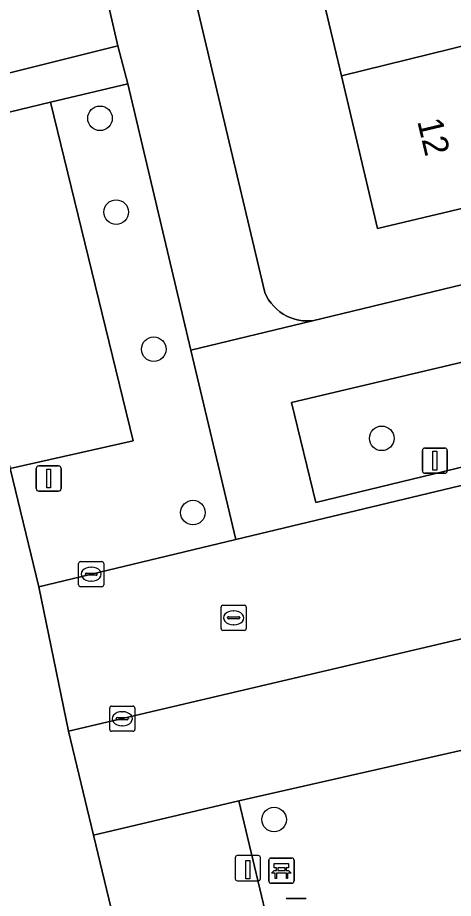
# Model space of a CAD drawing. Extents: x 158031 to 159244, y 380104 to 381214.
# Drawn here: x 158542.1 to 158559.44, y 380761.24 to 380796.3 of the extents above; entities that cross this region are included whole.
import ezdxf

# ---------------------------------------------------------------- set-up
doc = ezdxf.new("R2010")
doc.units = 0
for name, color, linetype in [('IMGEO_Afvalbak', 7, 'Continuous'), ('IMGEO_Bank', 7, 'Continuous'), ('IMGEO_Boom', 7, 'Continuous'), ('IMGEO_Erf', 7, 'Continuous'), ('IMGEO_Groenvoorziening', 7, 'Continuous'), ('IMGEO_Kolk', 7, 'Continuous'), ('IMGEO_Laadpaal', 7, 'Continuous'), ('IMGEO_Lichtmast', 7, 'Continuous'), ('IMGEO_Pand', 7, 'Continuous'), ('IMGEO_Pand_nummerreeks', 7, 'Continuous'), ('IMGEO_Parkeervlak_open', 7, 'Continuous'), ('IMGEO_Rijbaan_lokaal_open', 7, 'Continuous'), ('IMGEO_Rioolput', 7, 'Continuous'), ('IMGEO_Voetpad_open', 7, 'Continuous')]:
    doc.layers.add(name, color=color, linetype=linetype)

msp = doc.modelspace()

# ---------------------------------------------------------------- linework, layer by layer
at = {"layer": 'IMGEO_Afvalbak'}
for p, q in [((158552.789, 380761.24), (158553.579, 380761.24)), ((158553.579, 380761.24), (158552.789, 380761.24))]:
    msp.add_line(p, q, dxfattribs=at)
at = {"layer": 'IMGEO_Bank'}
for p, q in [((158552.1, 380761.919), (158552.1, 380762.76)), ((158552.1, 380762.76), (158552.1, 380761.919)), ((158552.175, 380762.844), (158553.016, 380762.844)), ((158553.016, 380762.844), (158552.175, 380762.844)), ((158553.1, 380762.769), (158553.1, 380761.928)), ((158553.1, 380761.928), (158553.1, 380762.769)), ((158552.409, 380762.35), (158552.409, 380762.456)), ((158552.453, 380762.456), (158552.453, 380762.35)), ((158552.741, 380762.462), (158552.459, 380762.462)), ((158552.459, 380762.344), (158552.741, 380762.344)), ((158552.747, 380762.35), (158552.747, 380762.456)), ((158552.791, 380762.456), (158552.791, 380762.35)), ((158552.797, 380762.242), (158552.404, 380762.242)), ((158553.025, 380761.844), (158552.184, 380761.844)), ((158552.184, 380761.844), (158553.025, 380761.844))]:
    msp.add_line(p, q, dxfattribs=at)
for points in [[(158552.403, 380762.462), (158552.317, 380762.462), (158552.317, 380762.623), (158552.88, 380762.623), (158552.88, 380762.462), (158552.797, 380762.462)], [(158552.347, 380762.242), (158552.205, 380762.242), (158552.317, 380762.344), (158552.403, 380762.344)], [(158552.797, 380762.344), (158552.88, 380762.344), (158552.992, 380762.242), (158552.853, 380762.242)], [(158552.397, 380762.235), (158552.397, 380762.028), (158552.354, 380762.028), (158552.354, 380762.235)], [(158552.847, 380762.235), (158552.847, 380762.028), (158552.803, 380762.028), (158552.803, 380762.235)]]:
    msp.add_lwpolyline(points, dxfattribs=at)
for centre, radius, start, end in [((158552.178, 380762.766), 0.0779, 92.4484, 184.2845), ((158552.178, 380762.766), 0.0779, 92.4484, 184.2845), ((158553.022, 380762.766), 0.0779, 2.4484, 94.2845), ((158553.022, 380762.766), 0.0779, 2.4484, 94.2845), ((158552.402, 380762.455), 0.00671, 2.8957, 87.1043), ((158552.402, 380762.351), 0.00671, 272.8957, 357.1043), ((158552.459, 380762.455), 0.00671, 92.8957, 177.1043), ((158552.459, 380762.351), 0.00671, 182.8957, 267.1043), ((158552.741, 380762.455), 0.00671, 2.8957, 87.1043), ((158552.741, 380762.351), 0.00671, 272.8957, 357.1043), ((158552.798, 380762.455), 0.00671, 92.8957, 177.1043), ((158552.798, 380762.351), 0.00671, 182.8957, 267.1043), ((158552.178, 380761.922), 0.0779, 182.4484, 274.2845), ((158552.178, 380761.922), 0.0779, 182.4484, 274.2845), ((158552.347, 380762.235), 0.00671, 2.8957, 87.1043), ((158552.404, 380762.235), 0.00671, 92.8957, 177.1043), ((158552.796, 380762.235), 0.00671, 2.8957, 87.1043), ((158552.853, 380762.235), 0.00671, 92.8957, 177.1043), ((158553.022, 380761.922), 0.0779, 272.4484, 4.2845), ((158553.022, 380761.922), 0.0779, 272.4484, 4.2845)]:
    msp.add_arc(centre, radius, start, end, dxfattribs=at)
at = {"layer": 'IMGEO_Boom'}
for centre in [(158545.379, 380792.292), (158546.022, 380788.557), (158547.52, 380783.101), (158556.593, 380779.552), (158549.077, 380776.596), (158552.309, 380764.378)]:
    msp.add_circle(centre, 0.489, dxfattribs=at)
at = {"layer": 'IMGEO_Erf'}
for points in [[(158544.566, 380816.468), (158551.938, 380785.363), (158552.008, 380785.214), (158552.091, 380785.071), (158552.186, 380784.936), (158552.293, 380784.811), (158552.411, 380784.695), (158552.539, 380784.591), (158552.675, 380784.498), (158552.82, 380784.418), (158552.971, 380784.351), (158553.127, 380784.298), (158553.287, 380784.259), (158553.45, 380784.234), (158553.615, 380784.224), (158553.78, 380784.229), (158553.836, 380784.234), (158575.794, 380789.538), (158568.094, 380822.042)], [(158562.747, 380800.007), (158563.667, 380796.124), (158564.626, 380792.079), (158569.966, 380793.345), (158570.391, 380791.548), (158565.064, 380790.285), (158565.138, 380789.974), (158556.423, 380787.909), (158554.986, 380793.976), (158553.597, 380799.838)]]:
    msp.add_lwpolyline(points, dxfattribs=at)
at = {"layer": 'IMGEO_Groenvoorziening'}
for points in [[(158538.226, 380793.212), (158546.085, 380795.171), (158543.309, 380807.269), (158533.158, 380804.845), (158533.865, 380801.959), (158534.897, 380797.743), (158537.111, 380798.246), (158538.129, 380793.613)], [(158546.49, 380793.669), (158543.412, 380792.934), (158546.695, 380779.447), (158541.806, 380778.346), (158542.939, 380773.643), (158550.781, 380775.523), (158548.998, 380783.065)], [(158577.413, 380782.673), (158576.522, 380786.533), (158552.994, 380780.981), (158553.963, 380777.002)]]:
    msp.add_lwpolyline(points, close=True, dxfattribs=at)
at = {"layer": 'IMGEO_Kolk'}
for p, q in [((158544.529, 380773.719), (158544.529, 380774.571)), ((158544.604, 380774.645), (158545.456, 380774.645)), ((158545.53, 380774.571), (158545.53, 380773.719)), ((158544.831, 380774.188), (158545.229, 380774.188)), ((158545.017, 380774.425), (158545.042, 380774.425)), ((158544.788, 380774.139), (158544.788, 380774.151)), ((158545.226, 380774.102), (158544.828, 380774.102)), ((158545.04, 380773.865), (158545.015, 380773.865)), ((158545.272, 380774.151), (158545.272, 380774.139)), ((158545.456, 380773.645), (158544.604, 380773.645)), ((158545.764, 380767.965), (158545.764, 380768.817)), ((158545.839, 380768.891), (158546.691, 380768.891)), ((158546.252, 380768.671), (158546.277, 380768.671)), ((158546.765, 380768.817), (158546.765, 380767.965)), ((158546.023, 380768.385), (158546.023, 380768.397)), ((158546.461, 380768.348), (158546.063, 380768.348)), ((158546.066, 380768.434), (158546.464, 380768.434)), ((158546.507, 380768.397), (158546.507, 380768.385)), ((158546.691, 380767.891), (158545.839, 380767.891)), ((158546.275, 380768.111), (158546.25, 380768.111))]:
    msp.add_line(p, q, dxfattribs=at)
for points in [[(158544.529, 380773.719), (158544.529, 380774.571)], [(158544.604, 380774.645), (158545.456, 380774.645)], [(158545.53, 380774.571), (158545.53, 380773.719)], [(158545.456, 380773.645), (158544.604, 380773.645)], [(158545.764, 380767.965), (158545.764, 380768.817)], [(158545.839, 380768.891), (158546.691, 380768.891)], [(158546.765, 380768.817), (158546.765, 380767.965)], [(158546.691, 380767.891), (158545.839, 380767.891)]]:
    msp.add_lwpolyline(points, dxfattribs=at)
for centre, radius, start, end in [((158544.606, 380774.569), 0.0765, 91.552, 178.448), ((158544.606, 380774.569), 0.0765, 91.552, 178.448), ((158545.454, 380774.569), 0.0765, 1.552, 88.448), ((158545.454, 380774.569), 0.0765, 1.552, 88.448), ((158544.828, 380774.148), 0.0403, 85.8775, 175.7526), ((158545.233, 380774.15), 0.0386, 1.7309, 96.639), ((158544.825, 380774.138), 0.0366, 178.938, 274.7102), ((158545.229, 380774.145), 0.043, 264.8664, 352.4533), ((158544.606, 380773.721), 0.0765, 181.552, 268.448), ((158544.606, 380773.721), 0.0765, 181.552, 268.448), ((158545.454, 380773.721), 0.0765, 271.552, 358.448), ((158545.454, 380773.721), 0.0765, 271.552, 358.448), ((158545.841, 380768.815), 0.0765, 91.552, 178.448), ((158545.841, 380768.815), 0.0765, 91.552, 178.448), ((158546.689, 380768.815), 0.0765, 1.552, 88.448), ((158546.689, 380768.815), 0.0765, 1.552, 88.448), ((158546.063, 380768.394), 0.0403, 85.8775, 175.7526), ((158546.06, 380768.384), 0.0366, 178.938, 274.7102), ((158546.464, 380768.391), 0.043, 264.8664, 352.4533), ((158546.468, 380768.396), 0.0386, 1.7309, 96.639), ((158545.841, 380767.967), 0.0765, 181.552, 268.448), ((158545.841, 380767.967), 0.0765, 181.552, 268.448), ((158546.689, 380767.967), 0.0765, 271.552, 358.448), ((158546.689, 380767.967), 0.0765, 271.552, 358.448)]:
    msp.add_arc(centre, radius, start, end, dxfattribs=at)
for centre, major_axis, ratio, start_param, end_param in [((158545.016, 380774.145), (-0.387, 0.002), 0.722429, 4.712389, 7.853982), ((158545.041, 380774.145), (-0.39, 0.002), 0.717154, 1.570796, 4.712389), ((158546.251, 380768.391), (-0.387, 0.002), 0.722429, 4.712389, 7.853982), ((158546.276, 380768.391), (-0.39, 0.002), 0.717154, 1.570796, 4.712389)]:
    msp.add_ellipse(centre, major_axis=major_axis, ratio=ratio, start_param=start_param, end_param=end_param, dxfattribs=at)
at = {"layer": 'IMGEO_Laadpaal'}
for p, q in [((158550.763, 380762.857), (158550.763, 380762.016)), ((158550.763, 380762.857), (158550.763, 380762.016)), ((158551.679, 380762.941), (158550.838, 380762.941)), ((158551.679, 380762.941), (158550.838, 380762.941)), ((158551.763, 380762.025), (158551.763, 380762.866)), ((158551.763, 380762.025), (158551.763, 380762.866)), ((158550.847, 380761.941), (158551.688, 380761.941)), ((158550.847, 380761.941), (158551.688, 380761.941))]:
    msp.add_line(p, q, dxfattribs=at)
msp.add_lwpolyline([(158551.178, 380762.754), (158551.338, 380762.754), (158551.338, 380762.021), (158551.178, 380762.021), (158551.178, 380762.754)], dxfattribs=at)
for centre, start, end in [((158550.841, 380762.863), 92.4484, 184.2845), ((158550.841, 380762.863), 92.4484, 184.2845), ((158551.685, 380762.863), 2.4484, 94.2845), ((158551.685, 380762.863), 2.4484, 94.2845), ((158550.841, 380762.019), 182.4484, 274.2845), ((158550.841, 380762.019), 182.4484, 274.2845), ((158551.685, 380762.019), 272.4484, 4.2845), ((158551.685, 380762.019), 272.4484, 4.2845)]:
    msp.add_arc(centre, 0.0779, start, end, dxfattribs=at)
at = {"layer": 'IMGEO_Lichtmast'}
for p, q in [((158558.31, 380779.163), (158559.1, 380779.163)), ((158559.1, 380779.163), (158558.31, 380779.163)), ((158558.21, 380778.263), (158558.21, 380779.063)), ((158558.21, 380779.063), (158558.21, 380778.263)), ((158559.2, 380779.063), (158559.2, 380778.263)), ((158559.2, 380778.263), (158559.2, 380779.063)), ((158542.94, 380778.453), (158543.73, 380778.453)), ((158543.73, 380778.453), (158542.94, 380778.453)), ((158542.84, 380777.553), (158542.84, 380778.353)), ((158542.84, 380778.353), (158542.84, 380777.553)), ((158543.83, 380778.353), (158543.83, 380777.553)), ((158543.83, 380777.553), (158543.83, 380778.353)), ((158559.1, 380778.163), (158558.31, 380778.163)), ((158558.31, 380778.163), (158559.1, 380778.163)), ((158543.73, 380777.453), (158542.94, 380777.453)), ((158542.94, 380777.453), (158543.73, 380777.453))]:
    msp.add_line(p, q, dxfattribs=at)
for points in [[(158558.63, 380779.038), (158558.78, 380779.038), (158558.78, 380778.288), (158558.63, 380778.288), (158558.63, 380779.038)], [(158543.26, 380778.328), (158543.41, 380778.328), (158543.41, 380777.578), (158543.26, 380777.578), (158543.26, 380778.328)]]:
    msp.add_lwpolyline(points, dxfattribs=at)
for centre, start, end in [((158558.31, 380779.063), 90, 180), ((158558.31, 380779.063), 90, 180), ((158559.1, 380779.063), 0, 90), ((158559.1, 380779.063), 360, 90), ((158542.94, 380778.353), 90, 180), ((158542.94, 380778.353), 90, 180), ((158543.73, 380778.353), 0, 90), ((158543.73, 380778.353), 360, 90), ((158558.31, 380778.263), 180, 270), ((158558.31, 380778.263), 180, 270), ((158559.1, 380778.263), 270, 0), ((158559.1, 380778.263), 270, 0), ((158542.94, 380777.553), 180, 270), ((158542.94, 380777.553), 180, 270), ((158543.73, 380777.553), 270, 0), ((158543.73, 380777.553), 270, 0)]:
    msp.add_arc(centre, 0.1, start, end, dxfattribs=at)
at = {"layer": 'IMGEO_Pand'}
for points in [[(158563.667, 380796.124), (158562.747, 380800.007), (158568.193, 380801.298), (158567.735, 380803.227), (158553.597, 380799.838), (158554.986, 380793.976)], [(158563.667, 380796.124), (158554.986, 380793.976), (158556.423, 380787.909), (158565.138, 380789.974), (158565.064, 380790.285), (158570.391, 380791.548), (158569.966, 380793.345), (158564.626, 380792.079)]]:
    msp.add_lwpolyline(points, close=True, dxfattribs=at)
at = {"layer": 'IMGEO_Parkeervlak_open'}
for points in [[(158543.412, 380792.934), (158538.573, 380791.773), (158541.806, 380778.346), (158546.695, 380779.447)], [(158547.375, 380754.387), (158553.139, 380755.776), (158550.898, 380765.127), (158545.124, 380763.759)]]:
    msp.add_lwpolyline(points, close=True, dxfattribs=at)
at = {"layer": 'IMGEO_Rijbaan_lokaal_open'}
for points in [[(158541.806, 380778.346), (158538.573, 380791.773), (158538.226, 380793.212), (158538.129, 380793.613), (158535.941, 380793.094), (158520.821, 380789.512), (158516.767, 380788.551), (158525.714, 380750), (158525.882, 380749.276), (158528.927, 380750), (158547.375, 380754.387), (158545.124, 380763.759), (158544.131, 380767.891), (158542.939, 380773.643)], [(158602.537, 380781.61), (158601.167, 380787.602), (158550.781, 380775.523), (158542.939, 380773.643), (158544.131, 380767.891)]]:
    msp.add_lwpolyline(points, close=True, dxfattribs=at)
at = {"layer": 'IMGEO_Rioolput'}
for p, q in [((158550.198, 380771.982), (158550.198, 380772.834)), ((158550.273, 380772.908), (158551.125, 380772.908)), ((158551.199, 380772.834), (158551.199, 380771.982)), ((158550.5, 380772.451), (158550.898, 380772.451)), ((158550.686, 380772.688), (158550.711, 380772.688)), ((158550.457, 380772.402), (158550.457, 380772.414)), ((158550.895, 380772.365), (158550.497, 380772.365)), ((158550.709, 380772.128), (158550.684, 380772.128)), ((158550.941, 380772.414), (158550.941, 380772.402)), ((158551.125, 380771.908), (158550.273, 380771.908))]:
    msp.add_line(p, q, dxfattribs=at)
for points in [[(158550.198, 380771.982), (158550.198, 380772.834)], [(158550.273, 380772.908), (158551.125, 380772.908)], [(158551.199, 380772.834), (158551.199, 380771.982)], [(158551.125, 380771.908), (158550.273, 380771.908)]]:
    msp.add_lwpolyline(points, dxfattribs=at)
for centre, radius, start, end in [((158550.275, 380772.832), 0.0765, 91.552, 178.448), ((158550.275, 380772.832), 0.0765, 91.552, 178.448), ((158551.123, 380772.832), 0.0765, 1.552, 88.448), ((158551.123, 380772.832), 0.0765, 1.552, 88.448), ((158550.497, 380772.411), 0.0403, 85.8775, 175.7526), ((158550.902, 380772.413), 0.0386, 1.7309, 96.639), ((158550.494, 380772.401), 0.0366, 178.938, 274.7102), ((158550.898, 380772.408), 0.043, 264.8664, 352.4533), ((158550.275, 380771.984), 0.0765, 181.552, 268.448), ((158550.275, 380771.984), 0.0765, 181.552, 268.448), ((158551.123, 380771.984), 0.0765, 271.552, 358.448), ((158551.123, 380771.984), 0.0765, 271.552, 358.448)]:
    msp.add_arc(centre, radius, start, end, dxfattribs=at)
for centre, major_axis, ratio, start_param, end_param in [((158550.685, 380772.408), (-0.387, 0.002), 0.722429, 4.712389, 7.853982), ((158550.71, 380772.408), (-0.39, 0.002), 0.717154, 1.570796, 4.712389)]:
    msp.add_ellipse(centre, major_axis=major_axis, ratio=ratio, start_param=start_param, end_param=end_param, dxfattribs=at)
at = {"layer": 'IMGEO_Voetpad_open'}
msp.add_lwpolyline([(158543.309, 380807.269), (158546.085, 380795.171), (158546.49, 380793.669), (158548.998, 380783.065), (158553.836, 380784.234), (158553.78, 380784.229), (158553.615, 380784.224), (158553.45, 380784.234), (158553.287, 380784.259), (158553.127, 380784.298), (158552.971, 380784.351), (158552.82, 380784.418), (158552.675, 380784.498), (158552.539, 380784.591), (158552.411, 380784.695), (158552.293, 380784.811), (158552.186, 380784.936), (158552.091, 380785.071), (158552.008, 380785.214), (158551.938, 380785.363), (158544.566, 380816.468)], dxfattribs=at)
for points in [[(158546.49, 380793.669), (158546.085, 380795.171), (158538.226, 380793.212), (158538.573, 380791.773), (158543.412, 380792.934)], [(158578.035, 380786.868), (158600.252, 380792.284), (158599.515, 380795.166), (158593.5, 380793.746), (158580.558, 380790.689), (158577.028, 380789.836), (158575.794, 380789.538), (158553.836, 380784.234), (158548.998, 380783.065), (158550.781, 380775.523), (158601.167, 380787.602), (158601.053, 380788.365), (158578.947, 380783.008)], [(158576.522, 380786.533), (158577.413, 380782.673), (158553.963, 380777.002), (158552.994, 380780.981)], [(158602.537, 380781.61), (158544.131, 380767.891), (158545.124, 380763.759), (158550.898, 380765.127), (158559.795, 380767.141), (158563.743, 380768.102), (158566.695, 380768.806), (158569.647, 380769.51), (158572.599, 380770.214), (158575.551, 380770.918), (158578.503, 380771.622), (158581.455, 380772.326), (158583.009, 380772.697), (158585.898, 380773.386), (158588.778, 380774.072), (158591.657, 380774.759), (158594.537, 380775.445), (158597.408, 380776.13), (158604.491, 380777.798)], [(158559.795, 380767.141), (158550.898, 380765.127), (158553.139, 380755.776), (158554.051, 380751.969), (158555.616, 380752.341), (158559.465, 380753.253), (158560.236, 380750), (158564.379, 380732.511), (158564.728, 380731.038), (158570.352, 380707.295), (158573.761, 380708.16), (158568.508, 380730.343), (158568.185, 380731.708), (158563.854, 380750)]]:
    msp.add_lwpolyline(points, close=True, dxfattribs=at)

# ---------------------------------------------------------------- texts
at = {"layer": 'IMGEO_Pand_nummerreeks'}
msp.add_text('12', height=1, rotation=283.3292, dxfattribs=at).set_placement((158558.001, 380792.178))

doc.saveas('drawing.dxf')
